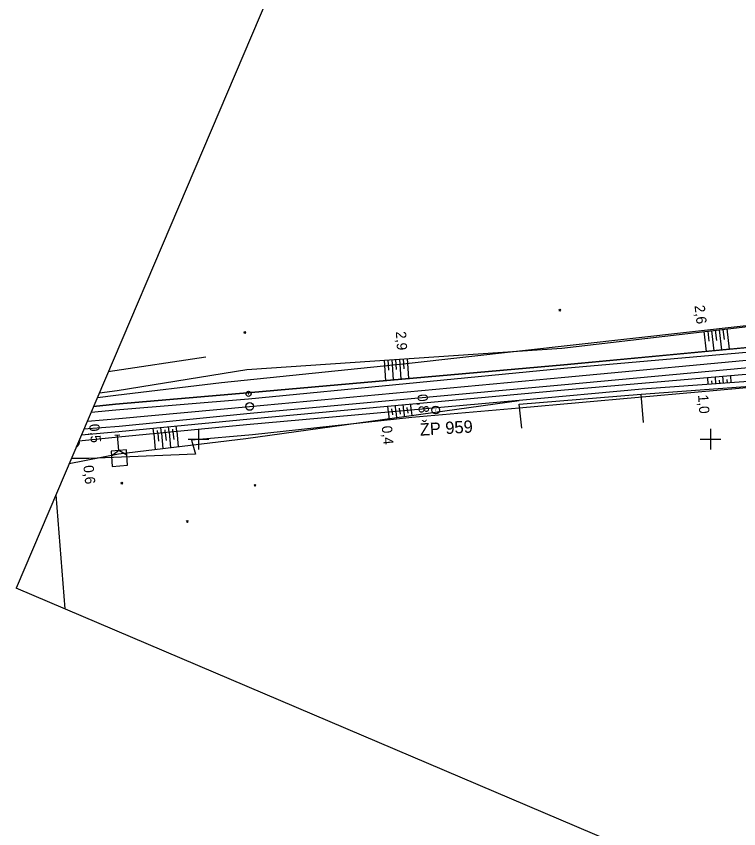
# Model space of a CAD drawing. Extents: x -805636 to -804553, y -1165340 to -1164656.
# Drawn here: x -805635.6 to -805494.5, y -1164976.1 to -1164817.4 of the extents above; entities that cross this region are included whole.
import ezdxf

# ---------------------------------------------------------------- set-up
doc = ezdxf.new("R2010")
doc.units = 0
for name, color, linetype in [('0381KM061-064P - Vrstva 1', 7, 'Continuous'), ('0381KM061-064P - Vrstva 17', 7, 'Continuous'), ('0381KM061-064P - Vrstva 4', 7, 'Continuous'), ('0381KM061-064P - Vrstva 48', 7, 'Continuous'), ('0381KM061-064P - Vrstva 49', 7, 'Continuous'), ('0381KM061-064P - Vrstva 7', 7, 'Continuous'), ('0381KM061-064P - Vrstva 8', 7, 'Continuous'), ('formát', 7, 'Continuous'), ('hran DP - hran DP', 7, 'Continuous'), ('krizky_1000 - Vrstva 1', 7, 'Continuous'), ('vyt_sit - stávající', 7, 'Continuous')]:
    doc.layers.add(name, color=color, linetype=linetype)

msp = doc.modelspace()

# ---------------------------------------------------------------- linework, layer by layer
at = {"layer": '0381KM061-064P - Vrstva 1'}
msp.add_lwpolyline([(-805621.7, -1164896.48), (-805615.58, -1164895.98), (-805590.01, -1164893.62), (-805528.48, -1164887.9), (-805486.76, -1164883.98), (-805461.3, -1164882.03), (-805437.69, -1164881.51), (-805413.27, -1164883.66)], dxfattribs=at)
at = {"layer": '0381KM061-064P - Vrstva 17'}
for p, q in [((-805598.57, -1164884.01), (-805617.61, -1164886.87)), ((-805513.07, -1164896.77), (-805513.54, -1164891.19))]:
    msp.add_line(p, q, dxfattribs=at)
msp.add_lwpolyline([(-805536.86, -1164897.86), (-805537.37, -1164893.17), (-805513.54, -1164891.19), (-805489.69, -1164889.49), (-805460.65, -1164887.61), (-805460.29, -1164888.19), (-805437.32, -1164886.99), (-805436.25, -1164891.59)], dxfattribs=at)
at = {"layer": '0381KM061-064P - Vrstva 4'}
for p, q in [((-805528.63, -1164885.47), (-805490.63, -1164881.9)), ((-805490.28, -1164882.82), (-805528.62, -1164886.23)), ((-805589.69, -1164890.91), (-805528.63, -1164885.47)), ((-805528.62, -1164886.23), (-805590.21, -1164892.16)), ((-805616.18, -1164893.18), (-805589.69, -1164890.91)), ((-805620.48, -1164893.61), (-805616.18, -1164893.18)), ((-805590.21, -1164892.16), (-805616.16, -1164894.34)), ((-805616.16, -1164894.34), (-805620.98, -1164894.78))]:
    msp.add_line(p, q, dxfattribs=at)
for points in [[(-805622.83, -1164899.13), (-805615.58, -1164898.49), (-805589.92, -1164896.02), (-805528.49, -1164890.34), (-805490.03, -1164887.06), (-805461.18, -1164884.75), (-805437.91, -1164883.87), (-805413.61, -1164886.43), (-805397.33, -1164889.69), (-805391.36, -1164890.97), (-805383.82, -1164892.41)], [(-805383.82, -1164892.41), (-805391.14, -1164890.05), (-805413.4, -1164885.24), (-805437.69, -1164883.08), (-805461.24, -1164883.62), (-805489.81, -1164885.79), (-805528.46, -1164889.37), (-805589.94, -1164895), (-805615.48, -1164897.55), (-805622.38, -1164898.08)]]:
    msp.add_lwpolyline(points, dxfattribs=at)
at = {"layer": '0381KM061-064P - Vrstva 48'}
for p, q in [((-805501.3, -1164879), (-805500.85, -1164882.86)), ((-805500.56, -1164878.91), (-805500.33, -1164880.85)), ((-805499.81, -1164878.83), (-805499.36, -1164882.72)), ((-805499.07, -1164878.74), (-805498.84, -1164880.7)), ((-805498.32, -1164878.66), (-805497.87, -1164882.58)), ((-805497.58, -1164878.57), (-805497.35, -1164880.54)), ((-805496.83, -1164878.48), (-805496.37, -1164882.44)), ((-805563.76, -1164884.57), (-805563.49, -1164888.58)), ((-805563.01, -1164884.52), (-805562.88, -1164886.51)), ((-805562.27, -1164884.47), (-805562, -1164888.44)), ((-805561.52, -1164884.42), (-805561.38, -1164886.4)), ((-805560.77, -1164884.36), (-805560.5, -1164888.31)), ((-805560.02, -1164884.31), (-805559.89, -1164886.28)), ((-805559.27, -1164884.26), (-805559.01, -1164888.18)), ((-805500.46, -1164889.32), (-805500.56, -1164887.96)), ((-805499.71, -1164889.27), (-805499.76, -1164888.58)), ((-805498.96, -1164889.21), (-805499.06, -1164887.83)), ((-805498.21, -1164889.16), (-805498.26, -1164888.46)), ((-805497.46, -1164889.11), (-805497.57, -1164887.7)), ((-805496.72, -1164889.05), (-805496.77, -1164888.34)), ((-805495.97, -1164889), (-805496.07, -1164887.57)), ((-805562.92, -1164894.73), (-805563.03, -1164893.53)), ((-805561.43, -1164894.6), (-805561.53, -1164893.4)), ((-805559.93, -1164894.46), (-805560.04, -1164893.26)), ((-805558.44, -1164894.33), (-805558.55, -1164893.12)), ((-805562.92, -1164894.73), (-805562.81, -1164895.99)), ((-805562.17, -1164894.66), (-805562.23, -1164894.06)), ((-805562.17, -1164894.66), (-805562.12, -1164895.27)), ((-805561.43, -1164894.6), (-805561.32, -1164895.78)), ((-805560.68, -1164894.53), (-805560.73, -1164893.93)), ((-805560.68, -1164894.53), (-805560.63, -1164895.1)), ((-805559.93, -1164894.46), (-805559.83, -1164895.57)), ((-805559.19, -1164894.4), (-805559.24, -1164893.79)), ((-805559.19, -1164894.4), (-805559.14, -1164894.93)), ((-805558.44, -1164894.33), (-805558.35, -1164895.36)), ((-805608.72, -1164898.95), (-805608.83, -1164897.84)), ((-805607.97, -1164898.88), (-805608.03, -1164898.32)), ((-805607.23, -1164898.81), (-805607.33, -1164897.7)), ((-805606.48, -1164898.74), (-805606.53, -1164898.18)), ((-805605.73, -1164898.67), (-805605.84, -1164897.55)), ((-805604.99, -1164898.59), (-805605.04, -1164898.04)), ((-805604.24, -1164898.52), (-805604.35, -1164897.41)), ((-805608.72, -1164898.95), (-805608.43, -1164902)), ((-805607.97, -1164898.88), (-805607.83, -1164900.4)), ((-805607.23, -1164898.81), (-805606.94, -1164901.82)), ((-805606.48, -1164898.74), (-805606.34, -1164900.24)), ((-805605.73, -1164898.67), (-805605.45, -1164901.65)), ((-805604.99, -1164898.59), (-805604.84, -1164900.08)), ((-805604.24, -1164898.52), (-805603.96, -1164901.47))]:
    msp.add_line(p, q, dxfattribs=at)
at = {"layer": '0381KM061-064P - Vrstva 49'}
for p, q in [((-805529.26, -1164875), (-805529.61, -1164874.64)), ((-805529.26, -1164874.64), (-805529.61, -1164875)), ((-805590.78, -1164879.37), (-805591.13, -1164879.01)), ((-805590.78, -1164879.01), (-805591.13, -1164879.37)), ((-805614.8, -1164908.81), (-805615.15, -1164908.45)), ((-805614.8, -1164908.45), (-805615.15, -1164908.81)), ((-805588.77, -1164909.21), (-805589.13, -1164908.86)), ((-805588.77, -1164908.86), (-805589.13, -1164909.21)), ((-805602, -1164916.26), (-805602.35, -1164915.9)), ((-805602, -1164915.9), (-805602.35, -1164916.26))]:
    msp.add_line(p, q, dxfattribs=at)
for points in [[(-805619.35, -1164890.95), (-805615.91, -1164890.53), (-805590.56, -1164886.39), (-805529.03, -1164882.21), (-805489.9, -1164877.68), (-805461.98, -1164874.39), (-805438.96, -1164873.66), (-805412.14, -1164878.2), (-805389.29, -1164884.48), (-805375.6, -1164889.14)], [(-805379.56, -1164889.14), (-805389.79, -1164885.89), (-805412.78, -1164881.05), (-805437.82, -1164878.81), (-805461.56, -1164879.34), (-805490.63, -1164881.9), (-805528.63, -1164885.47), (-805589.69, -1164890.91), (-805616.18, -1164893.18), (-805620.48, -1164893.61)], [(-805622.83, -1164899.13), (-805615.58, -1164898.49), (-805589.92, -1164896.02), (-805528.49, -1164890.34), (-805490.03, -1164887.06), (-805461.18, -1164884.75), (-805437.91, -1164883.87), (-805413.61, -1164886.43), (-805397.33, -1164889.69), (-805394.79, -1164892.28)], [(-805394.79, -1164892.28), (-805397.93, -1164890.9), (-805413.8, -1164887.77), (-805437.96, -1164885.62), (-805460.38, -1164886.37), (-805489.93, -1164888.57), (-805513.35, -1164890.24), (-805537.4, -1164892.44), (-805590.64, -1164897.22), (-805615.62, -1164899.61), (-805623.38, -1164900.43)], [(-805625.24, -1164904.79), (-805615.6, -1164902.86), (-805590.78, -1164899.89), (-805537.4, -1164892.44)]]:
    msp.add_lwpolyline(points, dxfattribs=at)
at = {"layer": '0381KM061-064P - Vrstva 7'}
for p, q in [((-805590.27, -1164891.15), (-805590.17, -1164891.14)), ((-805615.33, -1164899.2), (-805616.33, -1164899.28)), ((-805615.58, -1164902.23), (-805615.83, -1164899.24))]:
    msp.add_line(p, q, dxfattribs=at)
for points in [[(-805615.58, -1164902.23), (-805617.08, -1164902.35), (-805616.83, -1164905.34), (-805613.84, -1164905.1), (-805614.09, -1164902.11), (-805615.58, -1164902.23)], [(-805614, -1164903.1), (-805615.58, -1164902.23), (-805616.99, -1164903.35)]]:
    msp.add_lwpolyline(points, dxfattribs=at)
for centre, radius in [((-805590.22, -1164891.15), 0.5), ((-805590, -1164893.62), 0.75)]:
    msp.add_circle(centre, radius, dxfattribs=at)
at = {"layer": '0381KM061-064P - Vrstva 8'}
for p, q in [((-805623.32, -1164900.29), (-805623.86, -1164901.55)), ((-805627.84, -1164910.91), (-805626.08, -1164933.16))]:
    msp.add_line(p, q, dxfattribs=at)
msp.add_arc((-805624.26, -1164900.63), 1, 293.9534, 19.9498, dxfattribs=at)
at = {"layer": 'formát'}
for p in [(-805519.31, -1164655.82), (-805055.88, -1165175.77)]:
    msp.add_line(p, (-805635.59, -1164929.12), dxfattribs=at)
at = {"layer": 'hran DP - hran DP'}
for p, q in [((-805559.43, -1164885.25), (-805493.02, -1164877.83)), ((-805595.52, -1164888.96), (-805559.43, -1164885.25)), ((-805472.98, -1164888.24), (-805537.37, -1164893.92)), ((-805616.15, -1164891.42), (-805595.52, -1164888.96)), ((-805619.74, -1164891.88), (-805616.15, -1164891.42)), ((-805537.37, -1164893.92), (-805558.32, -1164895.77)), ((-805558.32, -1164895.77), (-805589.42, -1164899.19)), ((-805589.42, -1164899.19), (-805601.38, -1164900.18)), ((-805601.38, -1164900.18), (-805600.58, -1164902.92)), ((-805600.58, -1164902.92), (-805621.39, -1164903.78)), ((-805621.39, -1164903.78), (-805624.8, -1164903.76))]:
    msp.add_line(p, q, dxfattribs=at)
at = {"layer": 'krizky_1000 - Vrstva 1'}
for points in [[(-805600, -1164898), (-805600, -1164902)], [(-805500, -1164898), (-805500, -1164902)], [(-805602, -1164900), (-805598, -1164900)], [(-805502, -1164900), (-805498, -1164900)]]:
    msp.add_lwpolyline(points, dxfattribs=at)
at = {"layer": 'vyt_sit - stávající'}
msp.add_line((-805553.71, -1164894.29), (-805553.63, -1164894.35), dxfattribs=at)
msp.add_circle((-805553.67, -1164894.32), 0.756, dxfattribs=at)

# ---------------------------------------------------------------- texts
at = {"layer": '0381KM061-064P - Vrstva 48'}
for s, rotation, p in [('2,6', 276.6062, (-805503.14, -1164873.92)), ('2,9', 273.8809, (-805561.47, -1164878.99)), ('0,8', 275.1319, (-805557.27, -1164891.28)), ('1,0', 274.074, (-805502.45, -1164891.38)), ('0,5', 276.0149, (-805621.37, -1164897.12)), ('0,4', 275.1319, (-805564.22, -1164897.47)), ('0,6', 276.0149, (-805622.49, -1164905.2))]:
    msp.add_text(s, height=2, rotation=rotation, dxfattribs=at).set_placement(p)
at = {"layer": 'vyt_sit - stávající'}
msp.add_text('ŽP 959', height=2.4, rotation=3.5611, dxfattribs=at).set_placement((-805556.7, -1164899.34))

doc.saveas('drawing.dxf')
